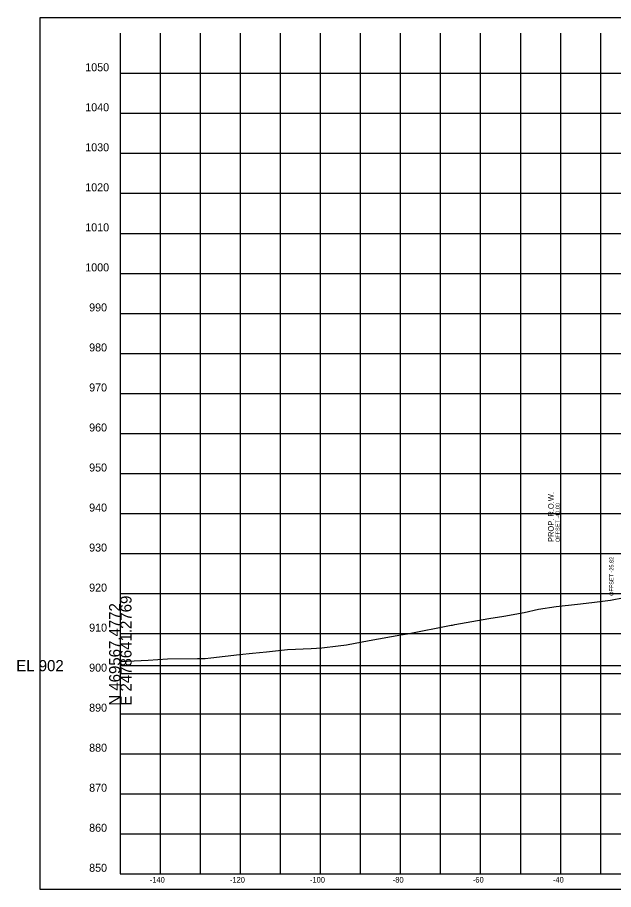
# Model space of a CAD drawing. Extents: x -26 to 2478923, y -10 to 469990.
# Drawn here: x -25.7 to 123.2, y 6444.1 to 6661.9 of the extents above; entities that cross this region are included whole.
import ezdxf

# ---------------------------------------------------------------- set-up
doc = ezdxf.new("R2010")
doc.units = 0
for name, color, linetype in [('DESIGN - ROW - Right-of-Way and Easement Labels', 7, 'Continuous'), ('DESIGN - ROW - Right-of-Way Linework', 7, 'Continuous'), ('DESIGN - SHEET - Corner Text', 7, 'Continuous'), ('DESIGN - SHEET - Light Grid', 7, 'Continuous'), ('DESIGN - SHEET - Linework', 7, 'Continuous'), ('DESIGN - SHEET - Plot Shape', 7, 'Continuous'), ('DESIGN - TYPICAL - Slope Tie Text', 7, 'Continuous'), ('SURVEY - GROUND - Top of Ground', 7, 'Continuous')]:
    doc.layers.add(name, color=color, linetype=linetype)

msp = doc.modelspace()

# ---------------------------------------------------------------- linework, layer by layer
at = {"layer": 'DESIGN - ROW - Right-of-Way Linework'}
msp.add_line((110, 6514.89), (110, 6546.89), dxfattribs=at)
at = {"layer": 'DESIGN - SHEET - Light Grid'}
msp.add_line((0, 6500), (150, 6500), dxfattribs=at)
at = {"layer": 'DESIGN - SHEET - Linework'}
for p, q in [((10, 6448), (10, 6658)), ((10, 6448), (10, 6658)), ((10, 6448), (10, 6658)), ((10, 6448), (10, 6658)), ((20, 6448), (20, 6658)), ((20, 6448), (20, 6658)), ((20, 6448), (20, 6658)), ((20, 6448), (20, 6658)), ((30, 6448), (30, 6658)), ((30, 6448), (30, 6658)), ((30, 6448), (30, 6658)), ((30, 6448), (30, 6658)), ((40, 6448), (40, 6658)), ((40, 6448), (40, 6658)), ((40, 6448), (40, 6658)), ((40, 6448), (40, 6658)), ((50, 6448), (50, 6658)), ((50, 6448), (50, 6658)), ((50, 6448), (50, 6658)), ((50, 6448), (50, 6658)), ((60, 6448), (60, 6658)), ((60, 6448), (60, 6658)), ((60, 6448), (60, 6658)), ((60, 6448), (60, 6658)), ((70, 6448), (70, 6658)), ((70, 6448), (70, 6658)), ((70, 6448), (70, 6658)), ((70, 6448), (70, 6658)), ((80, 6448), (80, 6658)), ((80, 6448), (80, 6658)), ((80, 6448), (80, 6658)), ((80, 6448), (80, 6658)), ((90, 6448), (90, 6658)), ((90, 6448), (90, 6658)), ((90, 6448), (90, 6658)), ((90, 6448), (90, 6658)), ((100, 6448), (100, 6658)), ((100, 6448), (100, 6658)), ((100, 6448), (100, 6658)), ((100, 6448), (100, 6658)), ((110, 6448), (110, 6658)), ((110, 6448), (110, 6658)), ((110, 6448), (110, 6658)), ((110, 6448), (110, 6658)), ((120, 6448), (120, 6658)), ((120, 6448), (120, 6658)), ((120, 6448), (120, 6658)), ((120, 6448), (120, 6658)), ((0, 6648), (300, 6648)), ((0, 6648), (300, 6648)), ((0, 6648), (300, 6648)), ((0, 6648), (300, 6648)), ((0, 6638), (300, 6638)), ((0, 6638), (300, 6638)), ((0, 6638), (300, 6638)), ((0, 6638), (300, 6638)), ((0, 6628), (300, 6628)), ((0, 6628), (300, 6628)), ((0, 6628), (300, 6628)), ((0, 6628), (300, 6628)), ((0, 6618), (300, 6618)), ((0, 6618), (300, 6618)), ((0, 6618), (300, 6618)), ((0, 6618), (300, 6618)), ((0, 6608), (300, 6608)), ((0, 6608), (300, 6608)), ((0, 6608), (300, 6608)), ((0, 6608), (300, 6608)), ((0, 6598), (300, 6598)), ((0, 6598), (300, 6598)), ((0, 6598), (300, 6598)), ((0, 6598), (300, 6598)), ((0, 6588), (300, 6588)), ((0, 6588), (300, 6588)), ((0, 6588), (300, 6588)), ((0, 6588), (300, 6588)), ((0, 6578), (300, 6578)), ((0, 6578), (300, 6578)), ((0, 6578), (300, 6578)), ((0, 6578), (300, 6578)), ((0, 6568), (300, 6568)), ((0, 6568), (300, 6568)), ((0, 6568), (300, 6568)), ((0, 6568), (300, 6568)), ((0, 6558), (300, 6558)), ((0, 6558), (300, 6558)), ((0, 6558), (300, 6558)), ((0, 6558), (300, 6558)), ((0, 6548), (300, 6548)), ((0, 6548), (300, 6548)), ((0, 6548), (300, 6548)), ((0, 6548), (300, 6548)), ((0, 6538), (300, 6538)), ((0, 6538), (300, 6538)), ((0, 6538), (300, 6538)), ((0, 6538), (300, 6538)), ((0, 6528), (300, 6528)), ((0, 6528), (300, 6528)), ((0, 6528), (300, 6528)), ((0, 6528), (300, 6528)), ((0, 6518), (300, 6518)), ((0, 6518), (300, 6518)), ((0, 6518), (300, 6518)), ((0, 6518), (300, 6518)), ((0, 6508), (300, 6508)), ((0, 6508), (300, 6508)), ((0, 6508), (300, 6508)), ((0, 6508), (300, 6508)), ((0, 6498), (300, 6498)), ((0, 6498), (300, 6498)), ((0, 6498), (300, 6498)), ((0, 6498), (300, 6498)), ((0, 6488), (300, 6488)), ((0, 6488), (300, 6488)), ((0, 6488), (300, 6488)), ((0, 6488), (300, 6488)), ((0, 6478), (300, 6478)), ((0, 6478), (300, 6478)), ((0, 6478), (300, 6478)), ((0, 6478), (300, 6478)), ((0, 6468), (300, 6468)), ((0, 6468), (300, 6468)), ((0, 6468), (300, 6468)), ((0, 6468), (300, 6468)), ((0, 6458), (300, 6458)), ((0, 6458), (300, 6458)), ((0, 6458), (300, 6458)), ((0, 6458), (300, 6458))]:
    msp.add_line(p, q, dxfattribs=at)
msp.add_lwpolyline([(0, 6658), (0, 6448), (300, 6448), (300, 6658)], dxfattribs=at)
msp.add_lwpolyline([(0, 6658), (0, 6448), (300, 6448), (300, 6658)], dxfattribs=at)
msp.add_lwpolyline([(0, 6658), (0, 6448), (300, 6448), (300, 6658)], dxfattribs=at)
msp.add_lwpolyline([(0, 6658), (0, 6448), (300, 6448), (300, 6658)], dxfattribs=at)
at = {"layer": 'DESIGN - SHEET - Plot Shape'}
msp.add_lwpolyline([(-20, 6661.94), (320, 6661.94), (320, 6444.06), (-20, 6444.06)], close=True, dxfattribs=at)
msp.add_lwpolyline([(-20, 6661.94), (320, 6661.94), (320, 6444.06), (-20, 6444.06)], close=True, dxfattribs=at)
msp.add_lwpolyline([(-20, 6661.94), (320, 6661.94), (320, 6444.06), (-20, 6444.06)], close=True, dxfattribs=at)
msp.add_lwpolyline([(-20, 6661.94), (320, 6661.94), (320, 6444.06), (-20, 6444.06)], close=True, dxfattribs=at)
at = {"layer": 'SURVEY - GROUND - Top of Ground'}
msp.add_lwpolyline([(0, 6501.03), (6.98, 6501.4), (11.78, 6501.67), (19.28, 6501.8), (21.22, 6501.81), (22.61, 6501.95), (29.77, 6502.76), (33, 6503.09), (36.55, 6503.44), (41.74, 6504.06), (47.67, 6504.26), (50.35, 6504.45), (54.4, 6504.95), (56.52, 6505.24), (62.19, 6506.27), (70.09, 6507.67), (71.69, 6507.97), (82.64, 6510.08), (82.98, 6510.15), (83.59, 6510.25), (92.04, 6511.74), (95.82, 6512.32), (100.89, 6513.25), (104.45, 6514.08), (108.9, 6514.77), (114.19, 6515.33), (117.77, 6515.78), (122.4, 6516.36), (125.87, 6517)], dxfattribs=at)

# ---------------------------------------------------------------- texts
at = {"layer": 'DESIGN - ROW - Right-of-Way and Easement Labels'}
for s, height, p in [('PROP. R.O.W.', 1.4, (108.25, 6530.89)), ('OFFSET -40.00', 1, (109.75, 6530.89))]:
    msp.add_text(s, height=height, rotation=90, dxfattribs=at).set_placement(p)
at = {"layer": 'DESIGN - SHEET - Corner Text'}
for s, height, p in [('1050', 2, (-8.75, 6648.5)), ('1050', 2, (-8.75, 6648.5)), ('1050', 2, (-8.75, 6648.5)), ('1050', 2, (-8.75, 6648.5)), ('1040', 2, (-8.75, 6638.5)), ('1040', 2, (-8.75, 6638.5)), ('1040', 2, (-8.75, 6638.5)), ('1040', 2, (-8.75, 6638.5)), ('1030', 2, (-8.75, 6628.5)), ('1030', 2, (-8.75, 6628.5)), ('1030', 2, (-8.75, 6628.5)), ('1030', 2, (-8.75, 6628.5)), ('1020', 2, (-8.75, 6618.5)), ('1020', 2, (-8.75, 6618.5)), ('1020', 2, (-8.75, 6618.5)), ('1020', 2, (-8.75, 6618.5)), ('1010', 2, (-8.75, 6608.5)), ('1010', 2, (-8.75, 6608.5)), ('1010', 2, (-8.75, 6608.5)), ('1010', 2, (-8.75, 6608.5)), ('1000', 2, (-8.75, 6598.5)), ('1000', 2, (-8.75, 6598.5)), ('1000', 2, (-8.75, 6598.5)), ('1000', 2, (-8.75, 6598.5)), ('990', 2, (-7.78, 6588.5)), ('990', 2, (-7.78, 6588.5)), ('990', 2, (-7.78, 6588.5)), ('990', 2, (-7.78, 6588.5)), ('980', 2, (-7.78, 6578.5)), ('980', 2, (-7.78, 6578.5)), ('980', 2, (-7.78, 6578.5)), ('980', 2, (-7.78, 6578.5)), ('970', 2, (-7.78, 6568.5)), ('970', 2, (-7.78, 6568.5)), ('970', 2, (-7.78, 6568.5)), ('970', 2, (-7.78, 6568.5)), ('960', 2, (-7.78, 6558.5)), ('960', 2, (-7.78, 6558.5)), ('960', 2, (-7.78, 6558.5)), ('960', 2, (-7.78, 6558.5)), ('950', 2, (-7.78, 6548.5)), ('950', 2, (-7.78, 6548.5)), ('950', 2, (-7.78, 6548.5)), ('950', 2, (-7.78, 6548.5)), ('940', 2, (-7.78, 6538.5)), ('940', 2, (-7.78, 6538.5)), ('940', 2, (-7.78, 6538.5)), ('940', 2, (-7.78, 6538.5)), ('930', 2, (-7.78, 6528.5)), ('930', 2, (-7.78, 6528.5)), ('930', 2, (-7.78, 6528.5)), ('930', 2, (-7.78, 6528.5)), ('920', 2, (-7.78, 6518.5)), ('920', 2, (-7.78, 6518.5)), ('920', 2, (-7.78, 6518.5)), ('920', 2, (-7.78, 6518.5)), ('910', 2, (-7.78, 6508.5)), ('910', 2, (-7.78, 6508.5)), ('910', 2, (-7.78, 6508.5)), ('910', 2, (-7.78, 6508.5)), ('900', 2, (-7.78, 6498.5)), ('900', 2, (-7.78, 6498.5)), ('900', 2, (-7.78, 6498.5)), ('900', 2, (-7.78, 6498.5)), ('890', 2, (-7.78, 6488.5)), ('890', 2, (-7.78, 6488.5)), ('890', 2, (-7.78, 6488.5)), ('890', 2, (-7.78, 6488.5)), ('880', 2, (-7.78, 6478.5)), ('880', 2, (-7.78, 6478.5)), ('880', 2, (-7.78, 6478.5)), ('880', 2, (-7.78, 6478.5)), ('870', 2, (-7.78, 6468.5)), ('870', 2, (-7.78, 6468.5)), ('870', 2, (-7.78, 6468.5)), ('870', 2, (-7.78, 6468.5)), ('860', 2, (-7.78, 6458.5)), ('860', 2, (-7.78, 6458.5)), ('860', 2, (-7.78, 6458.5)), ('860', 2, (-7.78, 6458.5)), ('850', 2, (-7.78, 6448.5)), ('850', 2, (-7.78, 6448.5)), ('850', 2, (-7.78, 6448.5)), ('850', 2, (-7.78, 6448.5)), ('-140', 1.4, (7.37, 6445.8)), ('-140', 1.4, (7.37, 6445.8)), ('-140', 1.4, (7.37, 6445.8)), ('-140', 1.4, (7.37, 6445.8)), ('-120', 1.4, (27.37, 6445.8)), ('-120', 1.4, (27.37, 6445.8)), ('-120', 1.4, (27.37, 6445.8)), ('-120', 1.4, (27.37, 6445.8)), ('-100', 1.4, (47.37, 6445.8)), ('-100', 1.4, (47.37, 6445.8)), ('-100', 1.4, (47.37, 6445.8)), ('-100', 1.4, (47.37, 6445.8)), ('-80', 1.4, (68.06, 6445.8)), ('-80', 1.4, (68.06, 6445.8)), ('-80', 1.4, (68.06, 6445.8)), ('-80', 1.4, (68.06, 6445.8)), ('-60', 1.4, (88.06, 6445.8)), ('-60', 1.4, (88.06, 6445.8)), ('-60', 1.4, (88.06, 6445.8)), ('-60', 1.4, (88.06, 6445.8)), ('-40', 1.4, (108.06, 6445.8)), ('-40', 1.4, (108.06, 6445.8)), ('-40', 1.4, (108.06, 6445.8)), ('-40', 1.4, (108.06, 6445.8))]:
    msp.add_text(s, height=height, dxfattribs=at).set_placement(p)
at = {"layer": 'DESIGN - SHEET - Light Grid'}
for s, p in [('E 2478641.2769', (2.8, 6490)), ('N 469567.4772', (0, 6490))]:
    msp.add_text(s, height=2.8, rotation=90, dxfattribs=at).set_placement(p)
msp.add_text('EL 902', height=2.8, dxfattribs=at).set_placement((-26, 6498.6))
at = {"layer": 'DESIGN - TYPICAL - Slope Tie Text'}
msp.add_text('OFFSET -25.82', height=1, rotation=90, dxfattribs=at).set_placement((123.18, 6517.44))

doc.saveas('drawing.dxf')
